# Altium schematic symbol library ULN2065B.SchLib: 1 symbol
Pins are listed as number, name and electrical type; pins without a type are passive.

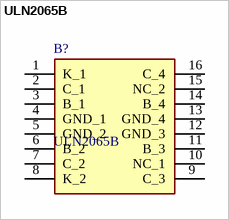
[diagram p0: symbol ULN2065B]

## ULN2065B
designator B?
ULN2065B, Darlington Transistor Array, NPN 1.75 A 80 V, Quad, 16-Pin, Power PDIP; Manufacturer_Name: STMicroelectronics; Geometry.Height: 5.1mm
footprint DIP880W50P254L2000H510Q16N
pins: 1 K_1, 2 C_1, 3 B_1, 4 GND_1, 5 GND_2, 6 B_2, 7 C_2, 8 K_2, 9 C_3, 10 NC_1, 11 B_3, 12 GND_3, 13 GND_4, 14 B_4, 15 NC_2, 16 C_4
